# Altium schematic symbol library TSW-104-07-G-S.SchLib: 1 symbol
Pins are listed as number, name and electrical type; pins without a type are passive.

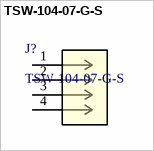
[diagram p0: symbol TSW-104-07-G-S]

## TSW-104-07-G-S
designator J?
Description; Manufacturer_Name: Samtec Inc
footprint CON4_1X4_TU_TSW
pins: 1, 2, 3, 4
